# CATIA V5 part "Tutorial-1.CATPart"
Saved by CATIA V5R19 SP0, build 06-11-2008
Part number: Part1
Bounding box of the stored display mesh (mm): x -150 to 150, y -150 to 150, z -127.513 to 0
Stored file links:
  D:\Shriniwas\v5_r19\Part files\c07\c07tut1.CATPart
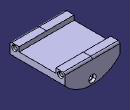
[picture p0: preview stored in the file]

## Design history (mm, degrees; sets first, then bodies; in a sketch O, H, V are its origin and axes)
Body1 (main body)
  Sketch1 on zx-plane, origin (0, 0, 0), H (-1, 0, 0), V (0, 0, 1)
    line L1 (0, 0) -> (150, 0)
    point P1 (150, 0)
    line L2 (150, 0) -> (150, -60)
    point P2 (150, -60)
    point P3 (-150, -60)
    point P4 (-150, 0)
    line L3 (-150, 0) -> (-150, -60)
    point P5 (0, 0)
    line L4 (0, 0) -> (-150, 0)
    arc A1 centre (0, 72.2876) radius 200 from (-150, -60) to (150, -60) ccw
    point P6 (0, 72.2876)
    distance L3 L2 = 300
    length L2 = 60
    radius A1 = 200
    horizontal: L1 H
    vertical: L2 V
    symmetry: P2 P3 V, P1 P4 V, L2 L3 V, O P5 V, L1 L4 V
    coincidence: P6 V, O P5
  Pad1: profile Sketch1, direction (0, 1, 0), length 150, mirrored extent
  Sketch2 on face of Pad1 from Sketch1.L3, origin (150, 0, 0), H (0, 1, 0), V (0, 0, 1)
    line L1 (-100, 0) -> (100, 0)
    reference projected line E1 (-150, 0) -> (150, 0) from edge [face of Pad1 from Sketch1.L3 | face of Pad1 from Sketch1.L4]
    line L2 (-100, 0) -> (-100, -25)
    line L3 (-100, -25) -> (100, -25)
    line L4 (100, 0) -> (100, -25)
    length L1 = 200
    distance L3 L1 = 25
    distance L4 V = 100
    coincidence: E1 L1
    vertical: L2 V, L4 V
    horizontal: L3 H
  Pocket1: profile Sketch2, direction (-1, 0, 0), through (limit type 3)
  Sketch3 on face of Pad1 from Sketch1.L3, origin (150, 95.7656, -28.4411), H (0, 1, 0), V (0, 0, 1)
    point P1 (29.2344, 8.4411)
    reference projected line E1 (-245.7656, 28.4411) -> (54.2344, 28.4411) from edge [face of Pad1 from Sketch1.L3 | face of Pad1 from Sketch1.L4]
    reference projected line E2 (54.2344, 28.4411) -> (54.2344, -31.5589) from edge [face of Pad1 from Sketch1.L3 | end face of Pad1]
    distance P1 E1 = 20
    distance P1 E2 = 25
  Hole1: placed by Sketch3, at (150, 125, -20) direction (-1, 0, 0), diameter 20, through (limit type 3), countersink depth 5, countersink angle 90
  Sketch4 on face of Pad1 from Sketch1.L3, origin (150, -127.9074, -34.2074), H (0, 1, 0), V (0, 0, 1)
    point P1 (2.9074, 14.2074)
    reference projected line E1 (-22.0926, 34.2074) -> (-22.0926, -25.7926) from edge [start face of Pad1 | face of Pad1 from Sketch1.L3]
    reference projected line E2 (-22.0926, 34.2074) -> (277.9074, 34.2074) from edge [face of Pad1 from Sketch1.L3 | face of Pad1 from Sketch1.L4]
    distance P1 E1 = 25
    distance P1 E2 = 20
  Hole2: placed by Sketch4, at (150, -125, -20) direction (-1, 0, 0), diameter 20, through (limit type 3), countersink depth 5, countersink angle 90
  Sketch5 on end face of Pad1, origin (-54.7231, 150, -53.7681), H (1, 0, 0), V (0, 0, -1)
    point P1 (54.7231, 46.2319)
    reference projected line E1 (54.7231, -53.7681) -> (204.7231, -53.7681) from edge [face of Pad1 from Sketch1.L4 | end face of Pad1]
    reference projected line E2 (-95.2769, 6.2319) -> (-95.2769, -53.7681) from edge [face of Pad1 from Sketch1.L2 | end face of Pad1]
    distance E1 P1 = 100
    distance E2 P1 = 150
  Hole3: placed by Sketch5, at (0, 150, -100) direction (0, -1, 0), diameter 30, through (limit type 3), counterbore diameter 40, counterbore depth 15
  Fillet1: radius 10, on edge [face of Pad1 from Sketch1.L1 | end face of Pad1]; edge [start face of Pad1 | face of Pad1 from Sketch1.L1]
